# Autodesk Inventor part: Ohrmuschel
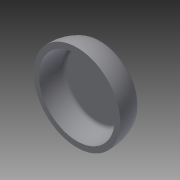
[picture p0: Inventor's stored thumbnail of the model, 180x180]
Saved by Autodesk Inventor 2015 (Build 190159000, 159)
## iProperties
Created: 2014-09
Part Number: Ohrmuschel
Material: Siliziumnitrid
Document SubType Name: Modeling
Designer: Andreas
Density: 3.18 g/cm^3
Appearance: Chrom - poliert - schwarz
Author: Andreas
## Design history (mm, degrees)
sketch "Skizze1"
  geometry: L1 (-27.49, 0)-(-31.5, 0); L2 (0, 19)-(-22.118, 19); L3 (0, 15)-(-22.118, 15) reference; L4 (0, 26.794)-(0, -6.547) reference; L5 (0, 19)-(0, 15); A1 r 29 centre (-2.564, 1.92) between (-28.34, 15.207) and (-31.5, 0); A2 r 7 centre (-22.118, 12) between (-22.118, 19) and (-28.34, 15.207); A3 r 3 centre (-22.118, 12) between (-22.118, 15) and (-24.785, 13.375); A4 r 25 centre (-2.564, 1.92) between (-24.785, 13.375) and (-27.49, 0); 2 further points
  constraints: 10 end point, 9 point on circle, 4 centre point, 3 horizontal, 2 tangent, 2 vertical, 1 point on line, 1 other
  dimensions: "d1" = 31.5 distance of point (0, 0) L1.end; "d2" = 26 distance of point (-26, 19) L2.start; "d4" = 19 distance between parallel lines of L1 L2; "d5" = 29 radius of A1; "d6" = 7 radius of A2; "d7" = 4 distance between parallel lines of L2 L3; "d8" = 22.11836 distance of L3.start L3.end; "d9" = 25 radius of A4; "d10" = 4.01021 distance of L1.start L1.end
revolve "Umdrehung1" sketch "Skizze1" stored, may be unused: angle "d12" = 90 deg
node "Volumenkörper1"
